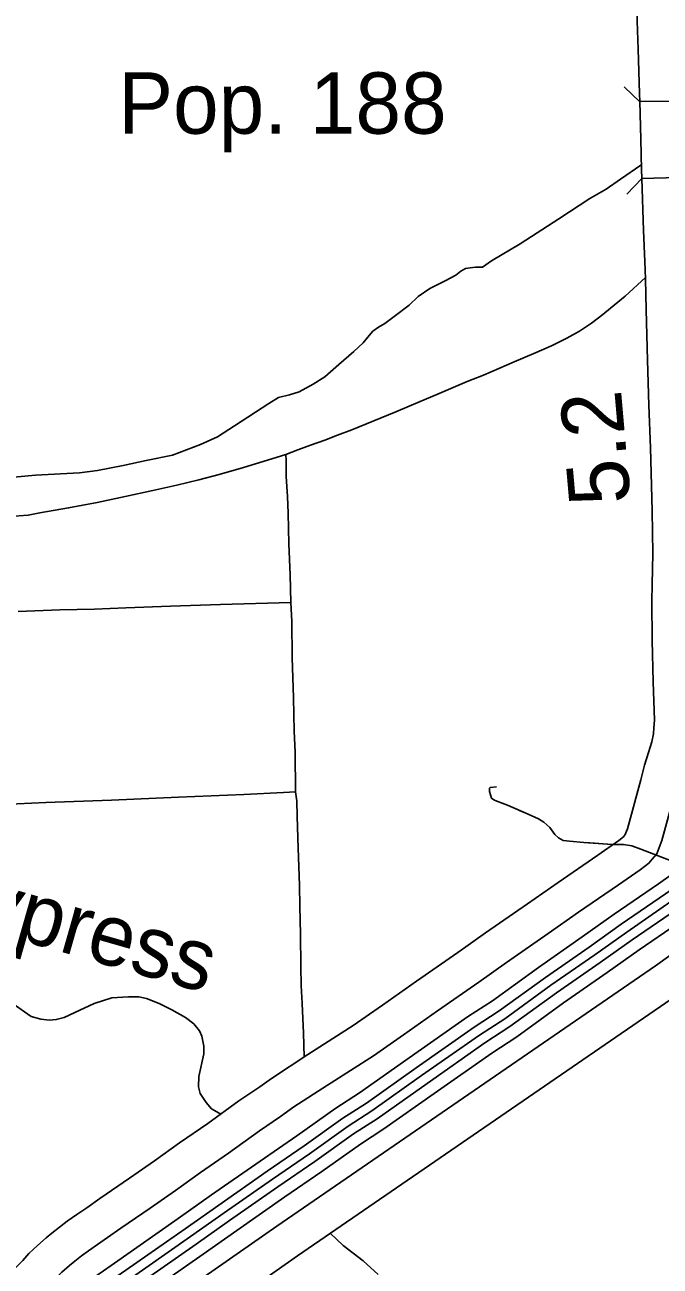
# Model space of a CAD drawing. Extents: x -117616 to 64730, y 54117 to 789866.
# Drawn here: x 63002.1 to 63089.6, y 54758.9 to 54929.9 of the extents above; entities that cross this region are included whole.
import ezdxf

# ---------------------------------------------------------------- set-up
doc = ezdxf.new("R2010")
doc.units = 0
for name, color, linetype in [('10', 7, 'Continuous'), ('15', 7, 'Continuous'), ('19', 7, 'Continuous'), ('33', 7, 'Continuous'), ('34', 7, 'Continuous'), ('35', 7, 'Continuous'), ('37', 7, 'Continuous'), ('43', 7, 'Continuous'), ('48', 7, 'Continuous'), ('6', 7, 'Continuous'), ('R_Draft', 7, 'Continuous')]:
    doc.layers.add(name, color=color, linetype=linetype)

msp = doc.modelspace()

# ---------------------------------------------------------------- linework, layer by layer
at = {"layer": '10'}
for p, q in [((63086.8, 54919.36), (63091.8, 54919.42)), ((63092.07, 54908.9), (63087.08, 54908.77))]:
    msp.add_line(p, q, dxfattribs=at)
for points in [[(63084.61, 54993.64), (63084.82, 54985.09), (63084.94, 54981.35), (63085.23, 54973.29), (63085.52, 54965.69), (63085.72, 54958), (63085.89, 54951.08), (63086.13, 54943.53), (63086.28, 54937.23), (63086.46, 54930.44), (63086.56, 54926.59), (63086.76, 54920.49), (63086.8, 54919.36)], [(63087.08, 54908.77), (63087.03, 54910), (63086.95, 54914.19), (63086.8, 54919.36)], [(63087.08, 54908.77), (63087.32, 54901.59), (63087.49, 54897.32)], [(63087.49, 54897.32), (63087.58, 54894.97), (63087.67, 54890.67), (63087.85, 54883.75), (63088.04, 54877.53), (63088.26, 54871.69), (63088.5, 54862.98), (63088.61, 54857.12), (63088.52, 54852.85), (63088.46, 54850.53), (63088.5, 54845.15), (63088.66, 54839.46), (63088.84, 54834.16), (63088.76, 54833.09)], [(63088.76, 54833.09), (63088.68, 54832.28), (63088.44, 54831.18), (63088.02, 54829.71), (63087.46, 54827.98), (63086.93, 54825.96), (63085.38, 54820.22), (63085.09, 54819.17), (63084.76, 54818.32), (63084.67, 54818.22), (63084.55, 54818.07), (63083.9, 54817.57), (63081.01, 54815.57), (63075.54, 54811.8), (63071.32, 54808.88), (63065.56, 54804.85), (63061.75, 54802.16), (63056.06, 54798.22), (63051.35, 54794.92), (63047.34, 54792.08), (63041.08, 54788.1), (63036.05, 54784.82)], [(63039.15, 54780.88), (63043.78, 54783.89), (63050.12, 54787.92), (63054.23, 54790.83), (63058.92, 54794.11), (63064.62, 54798.06), (63068.44, 54800.76), (63074.17, 54804.78), (63078.38, 54807.69), (63083.85, 54811.46), (63086.84, 54813.53), (63088.05, 54814.45), (63088.52, 54815.02), (63089.13, 54815.74), (63089.84, 54817.6), (63090.21, 54818.9), (63091.76, 54824.67), (63092.26, 54826.58), (63092.8, 54828.25), (63093.29, 54829.96), (63093.62, 54831.49), (63093.73, 54832.58)], [(63036.05, 54784.82), (63034.44, 54783.64), (63031.56, 54781.7), (63027.28, 54778.62), (63023.41, 54775.95), (63019.93, 54773.45), (63016.51, 54771.07), (63012.44, 54768.29), (63010.62, 54766.99), (63009.23, 54766.06), (63007.94, 54765.14), (63006.85, 54764.34), (63005.82, 54763.5), (63005.01, 54762.84), (63003.83, 54761.8), (63002.65, 54760.68), (63001.83, 54759.75), (63000.57, 54758.5), (62999.24, 54757.38)], [(62999.24, 54757.38), (63001.93, 54753.14), (63003.23, 54754.2), (63003.93, 54754.8), (63005.48, 54756.32), (63006.26, 54757.22), (63007.2, 54758.11), (63008.24, 54759.03), (63008.98, 54759.62), (63009.9, 54760.38), (63010.87, 54761.08), (63012.08, 54761.95), (63013.47, 54762.88), (63015.3, 54764.19), (63019.34, 54766.95), (63022.82, 54769.37), (63026.29, 54771.86), (63030.16, 54774.53), (63034.42, 54777.59), (63037.32, 54779.55), (63039.15, 54780.88)]]:
    msp.add_lwpolyline(points, dxfattribs=at)
at = {"layer": '15'}
for p, q in [((63088.98, 54800.32), (63122.69, 54824.79)), ((63036.81, 54764.46), (63088.98, 54800.32)), ((63091.87, 54796.24), (63039.65, 54760.35)), ((63007.61, 54744.16), (63036.81, 54764.46)), ((63039.65, 54760.35), (63010.29, 54739.94))]:
    msp.add_line(p, q, dxfattribs=at)
at = {"layer": '19'}
for points in [[(63002.99, 54751.45), (63005.51, 54753.16), (63013.96, 54759.04), (63023.21, 54765.51), (63027.82, 54768.76), (63034.49, 54773.42), (63039.58, 54776.9), (63044.95, 54780.72), (63048.2, 54782.82), (63055.02, 54787.65), (63063.05, 54793.27), (63066.49, 54795.51), (63072.83, 54800.1), (63078.88, 54804.3), (63083.28, 54807.43), (63089.39, 54811.62), (63097, 54817.02), (63101.49, 54819.97)], [(63102.45, 54818.57), (63097.96, 54815.61), (63090.36, 54810.23), (63084.26, 54806.04), (63079.85, 54802.91), (63073.81, 54798.71), (63067.45, 54794.11), (63064, 54791.86), (63055.99, 54786.26), (63049.15, 54781.41), (63045.91, 54779.32), (63040.55, 54775.51), (63035.45, 54772.02), (63028.8, 54767.36), (63024.19, 54764.11), (63014.93, 54757.65), (63006.47, 54751.76), (63003.9, 54750.02), (63002.99, 54751.45)], [(63005.29, 54747.82), (63007.94, 54749.61), (63016.42, 54755.51), (63025.68, 54761.99), (63030.29, 54765.24), (63036.93, 54769.88), (63042.04, 54773.38), (63047.36, 54777.16), (63050.61, 54779.26), (63057.49, 54784.13), (63065.45, 54789.71), (63068.92, 54791.96), (63075.31, 54796.59), (63081.35, 54800.78), (63085.75, 54803.91), (63091.85, 54808.1), (63099.43, 54813.47), (63103.91, 54816.42)], [(63104.9, 54815.04), (63100.38, 54812.06), (63092.82, 54806.7), (63086.72, 54802.51), (63082.33, 54799.39), (63076.3, 54795.2), (63069.88, 54790.56), (63066.4, 54788.3), (63058.47, 54782.74), (63051.56, 54777.85), (63048.32, 54775.75), (63043.01, 54771.98), (63037.9, 54768.48), (63031.27, 54763.84), (63026.66, 54760.59), (63017.39, 54754.12), (63008.9, 54748.21), (63006.2, 54746.38), (63005.29, 54747.82)]]:
    msp.add_lwpolyline(points, dxfattribs=at)
at = {"layer": '33'}
for points in [[(63038.03, 54870.76), (63039.69, 54871.38), (63041.46, 54872.02), (63043.42, 54872.72), (63045.18, 54873.41), (63047.12, 54874.17), (63050.17, 54875.39), (63053.21, 54876.63), (63056.53, 54878.07), (63058.83, 54879.02), (63063.03, 54880.79), (63065.27, 54881.7), (63069.5, 54883.5), (63072.19, 54884.66), (63074.63, 54885.73), (63076.75, 54886.79), (63078.51, 54887.76), (63080.16, 54888.85), (63081.71, 54890.06), (63082.79, 54890.93), (63084.79, 54892.57), (63087.58, 54895.13)], [(62986.99, 54861.48), (62989.08, 54861.56), (62992.28, 54861.69), (62997.47, 54862.03), (63002.53, 54862.4), (63004.15, 54862.71), (63008.12, 54863.4), (63012.04, 54864.14), (63015.93, 54864.99), (63019.71, 54865.81), (63023.03, 54866.54), (63026.04, 54867.25), (63028.87, 54868), (63032.21, 54868.98), (63035.52, 54869.97), (63038.03, 54870.76)]]:
    msp.add_lwpolyline(points, dxfattribs=at)
at = {"layer": '34'}
for points in [[(63038.03, 54870.76), (63038.07, 54869.93), (63038.11, 54867.72), (63038.25, 54864.97), (63038.35, 54862.66), (63038.45, 54858.45), (63038.62, 54854.18), (63038.72, 54850.37)], [(63001.17, 54849.13), (63006.92, 54849.36), (63011.69, 54849.46), (63016.02, 54849.65), (63022.14, 54849.86), (63029.04, 54850.08), (63038.72, 54850.37)], [(63038.72, 54850.37), (63038.86, 54847.77), (63038.91, 54842.81), (63039.12, 54837.22), (63039.21, 54832.65), (63039.33, 54829.75), (63039.38, 54824.27)], [(63039.38, 54824.27), (63037.72, 54824.2), (63032.26, 54823.92), (63023.27, 54823.55), (63014.01, 54823.14), (63004.98, 54822.8), (63001.04, 54822.65), (62997.02, 54822.43), (62992.94, 54822.26), (62986.94, 54822.17)], [(63039.38, 54824.27), (63039.48, 54823.62), (63039.55, 54823.06), (63039.61, 54820.9), (63039.74, 54816.54), (63039.91, 54811.42), (63039.96, 54808.51), (63040.06, 54804.68), (63040.11, 54800.18), (63040.17, 54797.6), (63040.3, 54795.15), (63040.47, 54791.06), (63040.55, 54787.76)]]:
    msp.add_lwpolyline(points, dxfattribs=at)
at = {"layer": '35'}
for points in [[(63086.94, 54910.62), (63084.15, 54908.66), (63082.19, 54907.29), (63079.91, 54906.02), (63075.63, 54903.2), (63070.31, 54899.78), (63066.39, 54897.43), (63065.12, 54896.58), (63064.74, 54896.55), (63064.17, 54896.55), (63063.44, 54896.45), (63062.81, 54896.36), (63062.14, 54896.01), (63061.48, 54895.47), (63059.99, 54894.68), (63057.9, 54893.6), (63056.28, 54892.52), (63055.02, 54891.32), (63052.96, 54889.76), (63051.66, 54888.81), (63050.8, 54888.27), (63050.01, 54887.74), (63049.28, 54886.88), (63048.68, 54886.15), (63047.41, 54884.95), (63045.36, 54883.17), (63043.42, 54881.46), (63041.81, 54880.45), (63039.88, 54879.4), (63038.55, 54878.99), (63037.03, 54878.61), (63035.7, 54877.78), (63030.95, 54874.68), (63028.63, 54873.19), (63026.29, 54872.11), (63022.43, 54870.65), (63018.82, 54869.92), (63015.62, 54869.22), (63012.1, 54868.56), (63009.6, 54868.24), (63003.55, 54867.89), (62994.62, 54867.1)], [(63029.08, 54779.92), (63028.84, 54780.01), (63027.82, 54780.62), (63027.05, 54781.49), (63026.23, 54782.72), (63026.02, 54783.64), (63026.08, 54785.08), (63026.74, 54788.21), (63026.74, 54789.23), (63026.49, 54790.61), (63026.13, 54791.38), (63025.36, 54792.31), (63024.23, 54793.18), (63022.34, 54794.25), (63020.6, 54795.12), (63018.86, 54795.84), (63017.78, 54796.05), (63016.35, 54796.05), (63014.09, 54795.89), (63011.64, 54795.12), (63008.97, 54793.89), (63007.49, 54793.18), (63006.41, 54792.92), (63005.49, 54792.82), (63004.31, 54792.97), (63002.98, 54793.33), (63000.32, 54795.18)], [(63050.76, 54757.82), (63048.71, 54759.66), (63045.94, 54761.81), (63044.14, 54763.49)]]:
    msp.add_lwpolyline(points, dxfattribs=at)
at = {"layer": '37'}
for points in [[(63086.8, 54919.33), (63084.64, 54921.41)], [(63085.01, 54906.59), (63087.08, 54908.77)]]:
    msp.add_lwpolyline(points, dxfattribs=at)
at = {"layer": '43'}
for points in [[(63067.06, 54824.98), (63066.2, 54824.89), (63066.11, 54824.77), (63066.11, 54824.31), (63066.38, 54823.42), (63066.69, 54823.19), (63067.13, 54823.01), (63068.56, 54822.43), (63071.44, 54821.2), (63072.85, 54820.57), (63073.57, 54820.09), (63074.4, 54819.39), (63075.1, 54818.39), (63075.61, 54817.95), (63076.23, 54817.6), (63077.14, 54817.47), (63079.08, 54817.3), (63083.02, 54817.05), (63084.57, 54817.02), (63085.71, 54816.84), (63086.96, 54816.4), (63090.55, 54815.03), (63092.82, 54814.13)], [(63070.21, 54821.72), (63071.44, 54821.2), (63072.85, 54820.57), (63073.57, 54820.09), (63074.4, 54819.39), (63075.1, 54818.39), (63075.61, 54817.95), (63076.23, 54817.6), (63076.71, 54817.53)], [(63079.34, 54817.29), (63083.02, 54817.05), (63084.57, 54817.02), (63085.71, 54816.84), (63086.96, 54816.4), (63087.15, 54816.33)]]:
    msp.add_lwpolyline(points, dxfattribs=at)
at = {"layer": 'R_Draft'}
msp.add_lwpolyline([(63007.21, 54750.69), (63015.67, 54756.58), (63024.93, 54763.05), (63029.55, 54766.3), (63036.19, 54770.95), (63041.29, 54774.44), (63046.64, 54778.24), (63049.88, 54780.34), (63056.74, 54785.2), (63064.73, 54790.79), (63068.19, 54793.03), (63074.56, 54797.65), (63080.6, 54801.84), (63085, 54804.97), (63091.1, 54809.16), (63098.69, 54814.54), (63103.26, 54817.54)], dxfattribs=at)

# ---------------------------------------------------------------- texts
at = {"layer": '35'}
msp.add_text('Cypress', height=8.448, rotation=344.039, dxfattribs=at).set_placement((62987.21, 54807.92))
at = {"layer": '48'}
msp.add_text('5.2', height=8.448, rotation=94.9654, dxfattribs=at).set_placement((63085.56, 54864.16))
at = {"layer": '6'}
msp.add_text('Pop. 188', height=8.448, dxfattribs=at).set_placement((63014.97, 54914.94))

doc.saveas('drawing.dxf')
